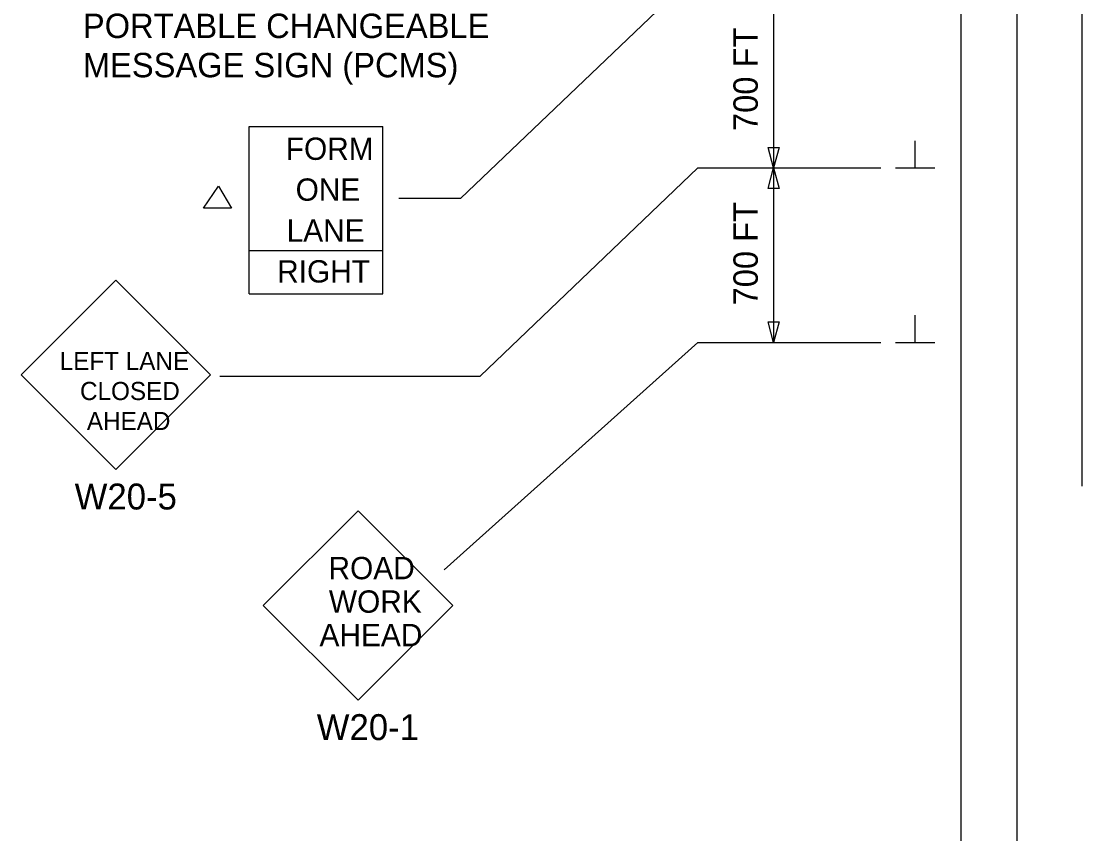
# Model space of a CAD drawing. Extents: x 15273 to 18137, y 1908 to 6555.
# Drawn here: x 16306.9 to 16611, y 2305.6 to 2540.6 of the extents above; entities that cross this region are included whole.
import ezdxf

# ---------------------------------------------------------------- set-up
doc = ezdxf.new("R2010")
doc.units = 0
for name, color, linetype in [('ALI_LEGAL_EX', 7, 'Continuous'), ('PAVT_EDGE_EX', 7, 'Continuous'), ('TRAFFIC_SIGNS_PR', 7, 'Continuous'), ('TYPICAL_TEXT_DIMEN_PR', 7, 'Continuous')]:
    doc.layers.add(name, color=color, linetype=linetype)

msp = doc.modelspace()

# ---------------------------------------------------------------- linework, layer by layer
at = {"layer": 'ALI_LEGAL_EX'}
msp.add_line((16610.98, 3236.46), (16610.98, 2407.28), dxfattribs=at)
at = {"layer": 'PAVT_EDGE_EX'}
for p, q in [((16576.35, 3138.78), (16576.35, 2305.55)), ((16592.35, 3138.78), (16592.35, 2305.55))]:
    msp.add_line(p, q, dxfattribs=at)
at = {"layer": 'TRAFFIC_SIGNS_PR'}
for p, q in [((16372.27, 2462.43), (16372.27, 2510.39)), ((16372.27, 2510.39), (16410.63, 2510.39)), ((16410.63, 2462.43), (16410.63, 2510.39)), ((16372.27, 2474.84), (16410.63, 2474.84)), ((16334.09, 2466.29), (16306.94, 2439.14)), ((16361.24, 2439.14), (16334.09, 2466.29)), ((16372.27, 2462.43), (16410.63, 2462.43)), ((16306.94, 2439.14), (16334.09, 2411.99)), ((16334.09, 2411.99), (16361.24, 2439.14)), ((16403.49, 2400.16), (16376.34, 2373.01)), ((16430.64, 2373.01), (16403.49, 2400.16)), ((16376.34, 2373.01), (16403.49, 2345.86)), ((16403.49, 2345.86), (16430.64, 2373.01))]:
    msp.add_line(p, q, dxfattribs=at)
at = {"layer": 'TYPICAL_TEXT_DIMEN_PR'}
for p, q in [((16494.38, 2548.48), (16432.89, 2489.71)), ((16522.62, 2548.48), (16522.62, 2498.48)), ((16563.23, 2498.48), (16563.23, 2506.26)), ((16522.62, 2498.48), (16521.05, 2504.34)), ((16521.05, 2504.34), (16522.62, 2504.34)), ((16522.62, 2504.34), (16524.2, 2504.34)), ((16524.2, 2504.34), (16522.62, 2498.48)), ((16500.94, 2498.48), (16438.49, 2438.78)), ((16500.94, 2498.48), (16553.35, 2498.48)), ((16521.05, 2492.61), (16522.62, 2498.48)), ((16522.62, 2498.48), (16522.62, 2448.48)), ((16522.62, 2498.48), (16524.2, 2492.61)), ((16557.6, 2498.48), (16568.85, 2498.48)), ((16522.62, 2492.61), (16521.05, 2492.61)), ((16524.2, 2492.61), (16522.62, 2492.61)), ((16432.89, 2489.71), (16415.24, 2489.71)), ((16522.62, 2448.48), (16521.05, 2454.34)), ((16521.05, 2454.34), (16522.62, 2454.34)), ((16522.62, 2454.34), (16524.2, 2454.34)), ((16524.2, 2454.34), (16522.62, 2448.48)), ((16563.23, 2448.48), (16563.23, 2456.26)), ((16500.94, 2448.48), (16428.16, 2383.26)), ((16500.94, 2448.48), (16553.35, 2448.48)), ((16557.6, 2448.48), (16568.85, 2448.48)), ((16363.91, 2438.78), (16438.49, 2438.78))]:
    msp.add_line(p, q, dxfattribs=at)
msp.add_lwpolyline([(16359.17, 2486.96), (16363.53, 2493.26), (16367.24, 2486.96)], close=True, dxfattribs=at)

# ---------------------------------------------------------------- texts
at = {"layer": 'TRAFFIC_SIGNS_PR'}
for s, height, p in [('PORTABLE CHANGEABLE', 7, (16324.62, 2535.73)), ('MESSAGE SIGN (PCMS)', 7, (16324.62, 2524.48)), ('FORM', 6.394, (16382.79, 2500.8)), ('ONE', 6.394, (16385.61, 2489.08)), ('LANE', 6.394, (16383.03, 2477.35)), ('RIGHT', 6.394, (16380.31, 2465.63)), ('LEFT LANE', 5.2, (16317.97, 2440.53)), ('CLOSED', 5.2, (16323.8, 2431.93)), ('AHEAD', 5.2, (16325.75, 2423.33)), ('W20-5', 7.44, (16322.26, 2400.55)), ('ROAD', 6.4, (16395.03, 2380.55)), ('WORK', 6.4, (16395.14, 2370.95)), ('AHEAD', 6.4, (16392.45, 2361.35)), ('W20-1', 7.44, (16391.66, 2334.42))]:
    msp.add_text(s, height=height, dxfattribs=at).set_placement(p)
at = {"layer": 'TYPICAL_TEXT_DIMEN_PR'}
for p in [(16518.1, 2509.07), (16518.1, 2459.07)]:
    msp.add_text('700 FT', height=7, rotation=90, dxfattribs=at).set_placement(p)

doc.saveas('drawing.dxf')
